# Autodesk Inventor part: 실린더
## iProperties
Manager: KYOUNG IL JANG
Company: 한국ATC센터
Created: 2012-10
Part Number: 실린더
Material: 기본값
Document SubType Name: 모델링
Density: 1 g/cm^3
Checked By: KYOUNG IL JANG
Vendor: CBT Solutions
Designer: KYOUNG IL JANG
Author: KYOUNG IL JANG
